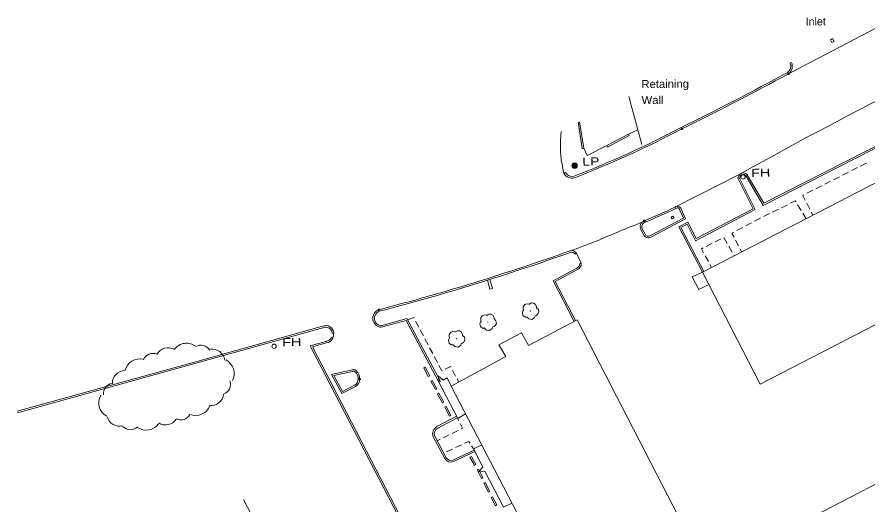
# Model space of a CAD drawing. Extents: x 2361284 to 2366480, y 6976556 to 6985346.
# Drawn here: x 2362444 to 2362954, y 6978671 to 6978964 of the extents above; entities that cross this region are included whole.
import ezdxf

# ---------------------------------------------------------------- set-up
doc = ezdxf.new("R2010")
doc.units = 0
doc.header["$LTSCALE"] = 1.9
doc.header["$PDMODE"] = 32
doc.header["$PDSIZE"] = 0.95
for name, color, linetype, lineweight in [('11', 7, 'Continuous', 13), ('16', 7, 'Continuous', 13), ('19', 7, 'Continuous', 13), ('26', 7, 'Continuous', 13), ('3', 7, 'Continuous', 13), ('4', 7, 'Continuous', 13), ('7', 7, 'Continuous', 13), ('8', 7, 'Continuous', 13), ('9', 7, 'Continuous', 13)]:
    doc.layers.add(name, color=color, linetype=linetype, lineweight=lineweight)

msp = doc.modelspace()

# ---------------------------------------------------------------- linework, layer by layer
at = {"layer": '11'}
for centre in [(2362879.443, 6978867.763), (2362598.293, 6978766.274)]:
    msp.add_circle(centre, 1.3, dxfattribs=at)
at = {"layer": '16'}
for points in [[(2362755.572, 6978789.3), (2362756.712, 6978788.241), (2362756.998, 6978786.654), (2362756.29, 6978785.327), (2362755.635, 6978784.781), (2362754.967, 6978784.564), (2362754.817, 6978784.553), (2362754.798, 6978784.443), (2362754.477, 6978783.54), (2362752.938, 6978782.375), (2362751.045, 6978782.657), (2362750.146, 6978783.599), (2362750.075, 6978783.728), (2362749.955, 6978783.707), (2362748.744, 6978783.825), (2362747.474, 6978784.823), (2362747.129, 6978786.46), (2362747.499, 6978787.484), (2362747.825, 6978787.927), (2362747.894, 6978787.977)], [(2362747.894, 6978787.987), (2362747.914, 6978787.998), (2362747.834, 6978788.067), (2362747.598, 6978788.695), (2362747.635, 6978789.975), (2362748.523, 6978791.274), (2362749.829, 6978791.756), (2362750.95, 6978791.567), (2362751.182, 6978791.439), (2362751.252, 6978791.439), (2362751.301, 6978791.48), (2362751.649, 6978791.773), (2362752.514, 6978792.222), (2362753.725, 6978792.153), (2362754.841, 6978791.564), (2362755.574, 6978790.141), (2362755.582, 6978789.281)], [(2362722.455, 6978781.324), (2362722.475, 6978781.335), (2362722.395, 6978781.404), (2362722.159, 6978782.032), (2362722.196, 6978783.312), (2362723.084, 6978784.611), (2362724.39, 6978785.093), (2362725.511, 6978784.904), (2362725.743, 6978784.776), (2362725.813, 6978784.776), (2362725.862, 6978784.817), (2362726.21, 6978785.11), (2362727.075, 6978785.559), (2362728.286, 6978785.49), (2362729.402, 6978784.901), (2362730.135, 6978783.478), (2362730.143, 6978782.618)], [(2362730.133, 6978782.637), (2362731.273, 6978781.578), (2362731.559, 6978779.991), (2362730.851, 6978778.664), (2362730.196, 6978778.118), (2362729.528, 6978777.901), (2362729.378, 6978777.89), (2362729.359, 6978777.78), (2362729.038, 6978776.877), (2362727.499, 6978775.712), (2362725.606, 6978775.994), (2362724.707, 6978776.936), (2362724.636, 6978777.065), (2362724.516, 6978777.044), (2362723.305, 6978777.162), (2362722.035, 6978778.16), (2362721.69, 6978779.797), (2362722.06, 6978780.821), (2362722.386, 6978781.264), (2362722.455, 6978781.314)], [(2362703.579, 6978771.394), (2362703.599, 6978771.405), (2362703.519, 6978771.474), (2362703.283, 6978772.102), (2362703.32, 6978773.382), (2362704.208, 6978774.681), (2362705.514, 6978775.163), (2362706.635, 6978774.974), (2362706.867, 6978774.846), (2362706.937, 6978774.846), (2362706.986, 6978774.887), (2362707.334, 6978775.18), (2362708.199, 6978775.629), (2362709.41, 6978775.56), (2362710.526, 6978774.971), (2362711.259, 6978773.548), (2362711.267, 6978772.688)], [(2362711.257, 6978772.707), (2362712.397, 6978771.648), (2362712.683, 6978770.061), (2362711.975, 6978768.734), (2362711.32, 6978768.188), (2362710.652, 6978767.971), (2362710.502, 6978767.96), (2362710.483, 6978767.85), (2362710.162, 6978766.947), (2362708.623, 6978765.782), (2362706.73, 6978766.064), (2362705.831, 6978767.006), (2362705.76, 6978767.135), (2362705.64, 6978767.114), (2362704.429, 6978767.232), (2362703.159, 6978768.23), (2362702.814, 6978769.867), (2362703.184, 6978770.891), (2362703.51, 6978771.334), (2362703.579, 6978771.384)]]:
    msp.add_lwpolyline(points, dxfattribs=at)
for centre in [(2362751.86, 6978787.415), (2362726.421, 6978780.752), (2362707.545, 6978770.822)]:
    msp.add_circle(centre, 0.1, dxfattribs=at)
for centre, radius, start, end in [((2362534.742, 6978757.731), 7.636, 60.91224, 150.91224), ((2362545.776, 6978758.956), 9.159, 53.0317, 143.0317), ((2362554.478, 6978760.843), 6.103, 31.4113, 121.4113), ((2362561.098, 6978756.976), 7.636, 7.78369, 97.78369), ((2362517.84, 6978749.569), 9.159, 76.30898, 166.30898), ((2362525.655, 6978755.904), 6.103, 67.34088, 157.34088), ((2362565.218, 6978749.869), 9.159, 333.48586, 63.48586), ((2362508.939, 6978744.071), 7.636, 90.38204, 180.38204), ((2362502.127, 6978737.972), 6.103, 98.12268, 188.12268), ((2362566.004, 6978743.436), 6.103, 289.90367, 19.90367), ((2362502.283, 6978732.409), 9.159, 150.56301, 240.56301), ((2362560.389, 6978738.367), 7.636, 264.02326, 354.02326), ((2362551.18, 6978733.936), 9.159, 247.97303, 337.97303), ((2362505.607, 6978725.944), 7.636, 195.12745, 285.12745), ((2362542.432, 6978728.203), 6.103, 242.58159, 332.58159), ((2362512.095, 6978722.403), 6.103, 223.76636, 313.76636), ((2362521.579, 6978725.152), 9.159, 234.63354, 324.63354), ((2362533.178, 6978726.776), 7.636, 237.54526, 327.54526)]:
    msp.add_arc(centre, radius, start, end, dxfattribs=at)
at = {"layer": '19'}
for p, q in [((2362939.055, 6978868.819), (2362942.618, 6978870.623)), ((2362944.4, 6978871.53), (2362947.963, 6978873.335)), ((2362933.701, 6978866.108), (2362937.274, 6978867.912)), ((2362923.012, 6978860.666), (2362926.574, 6978862.48)), ((2362928.356, 6978863.387), (2362931.919, 6978865.201)), ((2362917.668, 6978857.945), (2362921.231, 6978859.759)), ((2362902.408, 6978849.348), (2362905.992, 6978851.134)), ((2362912.113, 6978851.102), (2362914.205, 6978847.69)), ((2362919.439, 6978848.39), (2362917.654, 6978851.974)), ((2362897.033, 6978846.667), (2362900.616, 6978848.451)), ((2362915.251, 6978845.981), (2362917.232, 6978842.75)), ((2362921.223, 6978844.808), (2362920.326, 6978846.599)), ((2362881.021, 6978838.436), (2362884.574, 6978840.279)), ((2362886.345, 6978841.206), (2362889.898, 6978843.05)), ((2362875.697, 6978835.675), (2362879.249, 6978837.519)), ((2362862.711, 6978828.921), (2362866.274, 6978830.745)), ((2362867.997, 6978831.461), (2362869.94, 6978827.97)), ((2362876.745, 6978826.393), (2362874.921, 6978829.957)), ((2362857.366, 6978826.179), (2362860.93, 6978828.004)), ((2362870.906, 6978826.218), (2362872.85, 6978822.726)), ((2362858.623, 6978817.042), (2362856.709, 6978820.553)), ((2362873.826, 6978820.975), (2362874.081, 6978820.518)), ((2362878.559, 6978822.83), (2362877.652, 6978824.612)), ((2362860.537, 6978813.54), (2362859.58, 6978815.291)), ((2362684.997, 6978777.828), (2362683.132, 6978781.371)), ((2362687.788, 6978772.514), (2362685.924, 6978776.057)), ((2362690.578, 6978767.201), (2362688.714, 6978770.743)), ((2362693.369, 6978761.887), (2362691.505, 6978765.429)), ((2362696.15, 6978756.573), (2362694.296, 6978760.115)), ((2362707.057, 6978748.446), (2362705.212, 6978751.999)), ((2362708.901, 6978744.904), (2362707.974, 6978746.675)), ((2362708.911, 6978721.803), (2362708.34, 6978722.968)), ((2362699.649, 6978711.413), (2362703.221, 6978713.207)), ((2362705.013, 6978714.104), (2362708.587, 6978715.899)), ((2362696.066, 6978709.619), (2362697.857, 6978710.516)), ((2362705.232, 6978704.706), (2362701.619, 6978702.993)), ((2362710.659, 6978707.278), (2362707.045, 6978705.563)), ((2362717.762, 6978704.845), (2362716.696, 6978706.535))]:
    msp.add_line(p, q, dxfattribs=at)
for points in [[(2362949.745, 6978874.242), (2362953.188, 6978875.983), (2362953.259, 6978875.864)], [(2362916.757, 6978853.766), (2362915.279, 6978856.732), (2362915.886, 6978857.038)], [(2362907.784, 6978852.031), (2362910.66, 6978853.468), (2362911.066, 6978852.802)], [(2362891.669, 6978843.967), (2362892.943, 6978844.629), (2362895.242, 6978845.771)], [(2362874.014, 6978831.739), (2362872.781, 6978834.157), (2362873.925, 6978834.748)], [(2362855.753, 6978822.304), (2362854.45, 6978824.691), (2362855.585, 6978825.272)], [(2362682.205, 6978783.143), (2362681.981, 6978783.571), (2362678.693, 6978782.318)], [(2362699.076, 6978751.701), (2362698.777, 6978751.558), (2362697.076, 6978754.802)], [(2362704.296, 6978753.77), (2362704.102, 6978754.139), (2362700.878, 6978752.578)], [(2362710.378, 6978716.797), (2362711.155, 6978717.184), (2362709.788, 6978720.001)], [(2362715.62, 6978708.225), (2362714.94, 6978709.299), (2362712.471, 6978708.135)]]:
    msp.add_lwpolyline(points, dxfattribs=at)
at = {"layer": '26'}
msp.add_line((2362810.85, 6978916.033), (2362818.825, 6978887.116), dxfattribs=at)
for points in [[(2362855.093, 6978810.738), (2362848.879, 6978807.899), (2362852.962, 6978800.296)], [(2362697.172, 6978744.722), (2362696.616, 6978748.547), (2362699.61, 6978746.036)], [(2362713.002, 6978725.862), (2362708.34, 6978722.968), (2362697.122, 6978744.702), (2362697.172, 6978744.722)], [(2362699.61, 6978746.036), (2362702.007, 6978747.318), (2362704.363, 6978742.471)], [(2362723.366, 6978693.918), (2362717.762, 6978704.845), (2362722.72, 6978707.193)], [(2362724.63, 6978691.45), (2362720.804, 6978690.964), (2362723.367, 6978693.908)], [(2362740.842, 6978672.353), (2362735.716, 6978669.834), (2362724.63, 6978691.45)]]:
    msp.add_lwpolyline(points, dxfattribs=at)
at = {"layer": '3'}
for p, q in [((2362958.969, 6978956.913), (2362906.666, 6978929.575)), ((2362908.481, 6978936.401), (2362907.605, 6978936.013)), ((2362906.208, 6978930.418), (2362906.1, 6978930.349)), ((2362782.936, 6978884.755), (2362780.485, 6978900.603)), ((2362783.884, 6978884.904), (2362781.434, 6978900.753)), ((2362816.35, 6978896.084), (2362810.775, 6978893.38)), ((2362842.359, 6978897.425), (2362842.383, 6978897.437)), ((2362810.761, 6978893.373), (2362797.695, 6978886.529)), ((2362811.219, 6978892.53), (2362798.154, 6978885.685)), ((2362810.761, 6978893.373), (2362811.219, 6978892.53)), ((2362797.695, 6978886.529), (2362798.154, 6978885.685)), ((2362782.936, 6978884.755), (2362783.925, 6978884.834)), ((2362772.902, 6978870.339), (2362772.067, 6978869.871)), ((2362778.165, 6978868.239), (2362778.105, 6978868.217)), ((2362778.45, 6978867.323), (2362778.451, 6978867.322)), ((2362877.973, 6978869.708), (2362838.951, 6978849.876)), ((2362838.692, 6978849.664), (2362838.692, 6978849.663)), ((2362839.348, 6978848.963), (2362839.1, 6978848.794)), ((2362820.538, 6978840.581), (2362820.53, 6978840.577)), ((2362792.946, 6978829.948), (2362776.227, 6978823.568)), ((2362775.738, 6978823.472), (2362775.738, 6978823.473)), ((2362775.989, 6978822.545), (2362776.06, 6978822.569)), ((2362778.797, 6978821.542), (2362779.581, 6978822.099)), ((2362782.439, 6978816.017), (2362779.571, 6978822.129)), ((2362781.48, 6978815.968), (2362782.439, 6978816.017)), ((2362661.259, 6978787.232), (2362661.344, 6978787.258)), ((2362634.049, 6978774.113), (2362633.089, 6978774.074)), ((2362633.487, 6978771.188), (2362634.049, 6978774.113)), ((2362632.593, 6978771.54), (2362633.487, 6978771.188)), ((2362688.863, 6978753.668), (2362688.022, 6978753.206)), ((2362691.581, 6978748.654), (2362688.863, 6978753.668)), ((2362646.867, 6978751.039), (2362646.925, 6978750.989)), ((2362647.522, 6978751.74), (2362647.523, 6978751.74)), ((2362690.74, 6978748.192), (2362688.022, 6978753.206)), ((2362691.581, 6978748.654), (2362690.74, 6978748.192)), ((2362648.712, 6978746.662), (2362648.712, 6978746.644)), ((2362693.088, 6978745.829), (2362692.244, 6978745.371)), ((2362694.952, 6978740.306), (2362692.244, 6978745.371)), ((2362695.796, 6978740.764), (2362693.088, 6978745.829)), ((2362695.796, 6978740.764), (2362694.952, 6978740.306)), ((2362697.131, 6978738.126), (2362696.293, 6978737.658)), ((2362700.031, 6978732.853), (2362697.131, 6978738.126)), ((2362699.193, 6978732.385), (2362696.293, 6978737.658)), ((2362700.031, 6978732.853), (2362699.193, 6978732.385)), ((2362701.396, 6978730.148), (2362700.55, 6978729.694)), ((2362703.391, 6978724.311), (2362700.55, 6978729.694)), ((2362704.237, 6978724.764), (2362701.396, 6978730.148)), ((2362704.237, 6978724.764), (2362703.391, 6978724.311)), ((2362716.551, 6978700.309), (2362715.719, 6978699.83)), ((2362718.455, 6978695.016), (2362715.719, 6978699.83)), ((2362719.287, 6978695.495), (2362716.551, 6978700.309)), ((2362719.287, 6978695.495), (2362718.455, 6978695.016)), ((2362720.855, 6978692.629), (2362720.001, 6978692.191)), ((2362723.413, 6978687.563), (2362720.855, 6978692.629)), ((2362722.559, 6978687.125), (2362720.001, 6978692.191)), ((2362723.413, 6978687.563), (2362722.559, 6978687.125)), ((2362724.901, 6978684.688), (2362724.047, 6978684.25)), ((2362726.789, 6978678.816), (2362724.047, 6978684.25)), ((2362727.643, 6978679.253), (2362724.901, 6978684.688)), ((2362727.643, 6978679.253), (2362726.789, 6978678.816)), ((2362729.302, 6978676.148), (2362728.447, 6978675.712)), ((2362730.944, 6978670.746), (2362728.447, 6978675.712)), ((2362731.8, 6978671.182), (2362729.302, 6978676.148)), ((2362731.8, 6978671.182), (2362730.944, 6978670.746))]:
    msp.add_line(p, q, dxfattribs=at)
for points in [[(2363046.512, 6978949.765), (2363054.532, 6978935.08), (2362965.48, 6978888.441), (2362891.416, 6978850.685), (2362881.073, 6978868.647), (2362881.193, 6978868.487)], [(2363045.666, 6978949.307), (2363053.218, 6978935.477), (2362965.042, 6978889.297), (2362891.793, 6978851.959), (2362881.909, 6978869.125), (2362881.909, 6978869.125)], [(2362772.067, 6978869.871), (2362771.65, 6978871.644), (2362771.46, 6978872.536), (2362771.088, 6978874.45), (2362770.913, 6978875.408), (2362770.668, 6978876.848), (2362770.448, 6978878.296), (2362770.349, 6978879.025), (2362770.249, 6978879.861), (2362770.192, 6978880.419), (2362770.099, 6978881.534), (2362770.063, 6978882.091), (2362770.008, 6978883.207), (2362769.974, 6978884.322), (2362769.962, 6978885.065), (2362769.957, 6978886.552), (2362769.98, 6978888.228), (2362770.004, 6978889.067), (2362770.056, 6978890.324), (2362770.128, 6978891.581), (2362770.171, 6978892.21), (2362770.275, 6978893.467), (2362770.335, 6978894.095), (2362770.436, 6978895.038)], [(2362797.709, 6978886.536), (2362785.943, 6978880.713), (2362783.874, 6978884.934)], [(2362876.522, 6978866.594), (2362876.523, 6978866.594), (2362885.404, 6978848.707), (2362851.382, 6978830.813), (2362846.327, 6978840.736), (2362840.854, 6978837.924), (2362855.123, 6978810.748)], [(2362877.472, 6978866.738), (2362877.379, 6978867.022), (2362886.678, 6978848.289), (2362850.964, 6978829.509), (2362845.909, 6978839.442), (2362842.158, 6978837.516), (2362855.968, 6978811.196)], [(2362823.587, 6978832.555), (2362823.624, 6978832.57), (2362843.645, 6978843.09), (2362841.376, 6978848.158)], [(2362824.071, 6978831.725), (2362824.072, 6978831.724), (2362844.889, 6978842.662), (2362842.253, 6978848.546)], [(2362818.169, 6978836.268), (2362818.168, 6978836.268), (2362819.86, 6978832.954), (2362819.86, 6978832.953)], [(2362819.033, 6978836.686), (2362819.024, 6978836.706), (2362820.716, 6978833.392), (2362820.713, 6978833.393)], [(2362778.2, 6978781.184), (2362765.538, 6978805.476), (2362779.398, 6978812.928), (2362779.516, 6978812.98)], [(2362779.056, 6978781.633), (2362766.832, 6978805.077), (2362779.857, 6978812.083), (2362779.856, 6978812.082)], [(2362662.569, 6978778.642), (2362662.258, 6978778.612), (2362677.928, 6978782.881), (2362697.968, 6978745.15)], [(2362662.507, 6978777.684), (2362662.507, 6978777.684), (2362677.438, 6978781.756), (2362697.122, 6978744.702)], [(2362627.23, 6978778.249), (2362627.229, 6978778.249), (2362550.499, 6978756.838), (2362444.144, 6978727.376)], [(2362627.638, 6978777.38), (2362627.488, 6978777.321), (2362550.758, 6978755.911), (2362444.403, 6978726.448)], [(2362771.151, 6978501.58), (2362771.407, 6978501.655), (2362759.994, 6978496.616), (2362713.963, 6978584.834), (2362619.991, 6978766.509), (2362629.315, 6978769.218), (2362629.512, 6978769.258)], [(2362771.019, 6978502.531), (2362771.018, 6978502.531), (2362760.432, 6978497.861), (2362714.819, 6978585.272), (2362621.376, 6978765.913), (2362629.584, 6978768.301), (2362629.584, 6978768.301)], [(2362645.129, 6978752.186), (2362645.129, 6978752.188), (2362632.633, 6978749.459), (2362638.943, 6978737.987), (2362647.004, 6978742.105)], [(2362645.415, 6978751.27), (2362645.338, 6978751.25), (2362634.09, 6978748.793), (2362639.332, 6978739.262), (2362646.566, 6978742.961)], [(2362707.657, 6978724.301), (2362695.895, 6978718.109), (2362695.895, 6978718.109)], [(2362708.105, 6978723.455), (2362696.343, 6978717.263), (2362696.345, 6978717.261)], [(2362694.456, 6978712.663), (2362694.385, 6978712.823), (2362701.413, 6978699.461), (2362701.415, 6978699.461)], [(2362693.54, 6978712.376), (2362693.54, 6978712.375), (2362700.567, 6978699.013), (2362700.567, 6978699.012)], [(2362705.454, 6978698.043), (2362705.426, 6978698.029), (2362718.179, 6978704.1)], [(2362705.835, 6978697.162), (2362705.835, 6978697.163), (2362718.588, 6978703.234)]]:
    msp.add_lwpolyline(points, dxfattribs=at)
for centre, radius, start, end in [((2364245.803, 6976414.864), 2810.199, 115.28082, 119.12638), ((2362903.352, 6978934.11), 4.658, 306.15417, 24.07502), ((2362903.352, 6978934.11), 5.618, 306.15417, 24.07502), ((2362065.626, 6980478.867), 1761.895, 296.15907, 298.49551), ((2362065.626, 6980478.867), 1762.855, 296.15907, 298.49551), ((2362559.661, 6979434.057), 606.542, 291.10922, 297.78024), ((2362559.661, 6979434.057), 607.502, 291.10922, 297.78024), ((2362776.828, 6978872.529), 5.453, 209.1705, 287.30965), ((2362776.828, 6978872.529), 4.493, 209.17049, 287.30964), ((2362879.591, 6978867.06), 3.104, 41.69982, 188.64074), ((2362879.591, 6978867.06), 2.144, 41.69981, 188.64074), ((2362840.157, 6978848.099), 2.144, 9.08136, 133.12386), ((2362644.463, 6979263.567), 457.21, 292.60036, 295.13891), ((2362644.463, 6979263.567), 458.17, 292.60036, 295.13892), ((2362840.157, 6978848.099), 1.184, 9.08136, 133.12386), ((2363346.908, 6977523.028), 1419.476, 111.83538, 112.97052), ((2362821.603, 6978837.931), 3.816, 112.08106, 205.83417), ((2362821.603, 6978837.931), 2.856, 112.08105, 205.83415), ((2362822.548, 6978834.338), 3.024, 207.24155, 300.23596), ((2362822.548, 6978834.338), 2.064, 207.24156, 300.23596), ((2362313.775, 6980120.251), 1376.605, 284.61042, 289.60789), ((2362313.775, 6980120.251), 1377.565, 284.61042, 289.60789), ((2362776.672, 6978820.021), 3.575, 35.55576, 105.14408), ((2362776.672, 6978820.021), 2.615, 35.55577, 105.14408), ((2362778.44, 6978815.826), 3.043, 290.72266, 2.73661), ((2362778.44, 6978815.826), 4.003, 290.72264, 2.7366), ((2362662.857, 6978783.078), 5.405, 109.89544, 266.28896), ((2362662.857, 6978783.078), 4.446, 109.89544, 266.28896), ((2362629.267, 6978773.918), 4.786, 2.34543, 115.19361), ((2362629.267, 6978773.918), 3.826, 2.34543, 115.19361), ((2362629.244, 6978772.842), 3.594, 274.28282, 338.70838), ((2362629.244, 6978772.842), 4.553, 274.28282, 338.70838), ((2362645.905, 6978749.704), 2.6, 51.53313, 107.36954), ((2362645.905, 6978749.704), 1.64, 51.53312, 107.36954), ((2362642.893, 6978746.786), 5.821, 358.60397, 46.93989), ((2362642.893, 6978746.786), 6.781, 358.60398, 46.9399), ((2362644.111, 6978746.859), 4.605, 301.32156, 357.54763), ((2362644.111, 6978746.859), 5.565, 301.32157, 357.54764), ((2362698.169, 6978713.824), 4.851, 117.96239, 197.36944), ((2362698.169, 6978713.824), 3.891, 117.9624, 197.36945), ((2362704.202, 6978700.938), 4.114, 207.92081, 293.37699), ((2362704.202, 6978700.938), 3.154, 207.92082, 293.377)]:
    msp.add_arc(centre, radius, start, end, dxfattribs=at)
for p in [(2362906.666, 6978929.574), (2362842.806, 6978896.575), (2362820.169, 6978841.467), (2362661.017, 6978788.161), (2362649.671, 6978746.621)]:
    msp.add_point(p, dxfattribs=at)
at = {"layer": '4'}
for radius in [1.6, 1.3, 1, 0.539, 0.192]:
    msp.add_circle((2362778.463, 6978874.542), radius, dxfattribs=at)
at = {"layer": '7'}
msp.add_lwpolyline([(2363103.109, 6978853.588), (2363068.529, 6978920.703), (2362855.093, 6978810.738), (2362889.673, 6978743.623)], close=True, dxfattribs=at)
for points in [[(2362888.281, 6978647.134), (2362857.689, 6978631.282), (2362779.922, 6978782.081), (2362750.715, 6978766.832), (2362746.563, 6978774.353), (2362733.061, 6978767.145), (2362737.128, 6978760.083), (2362704.363, 6978742.471), (2362817.203, 6978525.552), (2362848.848, 6978541.923), (2362846.702, 6978546.803), (2362863.642, 6978555.415), (2362870.298, 6978542.127), (2362927.431, 6978571.542)], [(2362927.431, 6978571.542), (2363056.753, 6978638.295), (2363017.084, 6978713.822), (2362888.281, 6978647.134)], [(2362462.946, 6978336.358), (2362685.503, 6978452.391), (2362689.369, 6978464.208), (2362579.929, 6978674.474)]]:
    msp.add_lwpolyline(points, dxfattribs=at)
at = {"layer": '8'}
for points in [[(2362934.073, 6978948.956), (2362933.067, 6978950.666), (2362931.753, 6978950.024), (2362932.659, 6978948.292)], [(2362838.113, 6978843.248), (2362837.382, 6978844.351), (2362836.298, 6978843.711), (2362836.969, 6978842.577)]]:
    msp.add_lwpolyline(points, close=True, dxfattribs=at)
msp.add_lwpolyline([(2362727.649, 6978806.326), (2362729.249, 6978800.96), (2362727.533, 6978800.494), (2362726.192, 6978805.872)], dxfattribs=at)
at = {"layer": '9'}
msp.add_line((2362852.962, 6978800.296), (2362858.913, 6978803.323), dxfattribs=at)

# ---------------------------------------------------------------- texts
at = {"layer": '26', "width": 1.05}
for s, p in [('Retaining', (2362818.533, 6978920.986)), ('Wall', (2362818.624, 6978911.386))]:
    msp.add_text(s, height=4.799, rotation=0.545, dxfattribs=at).set_placement(p)
at = {"layer": '4'}
for s, width, p in [('  LP', 1.3, (2362778.463, 6978874.542)), ('  FH', 1.35, (2362879.442, 6978867.762)), ('  FH', 1.35, (2362598.292, 6978766.273))]:
    msp.add_text(s, height=4.799, rotation=0.545, dxfattribs=dict(at, width=width)).set_placement(p)
at = {"layer": '8'}
msp.add_text('Inlet', height=4.799, rotation=0.545, dxfattribs=at).set_placement((2362916.922, 6978958.502))

doc.saveas('drawing.dxf')
